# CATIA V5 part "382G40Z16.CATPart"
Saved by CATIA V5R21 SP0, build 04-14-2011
Part number: 382G40Z16
Bounding box of the stored display mesh (mm): x -131.403 to 131.403, y -131.403 to 131.403, z -20 to 20
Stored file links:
  C:\Users\ALI OZGUN\Desktop\alhan\TESLIMEDILEN3\382G40Z16.CATPart
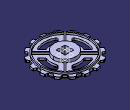
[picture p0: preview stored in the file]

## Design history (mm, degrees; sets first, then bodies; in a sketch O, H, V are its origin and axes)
Body1 (main body)
  Sketch1 on xy-plane, origin (0, 0, 0), H (1, 0, 0), V (0, 1, 0)
    circle A1 centre (0, 0) radius 132.5
    radius A1 = 132.5
  Pad1: profile Sketch1, direction (0, 0, 1), length 4.85, mirrored extent
  Sketch2 on end face of Pad1, origin (0, 0, 4.85), H (1, 0, 0), V (0, 1, 0)
    line L1 (-15.0612, 130.2617) -> (-10.5897, 120.8269)
    arc A1 centre (0, 0) radius 120 from (8.6385, 119.6887) to (-8.6385, 119.6887) ccw
    projected circle E1 centre (0, 0) radius 132.5 from edge [face of Pad1 from Sketch1.A1 | end face of Pad1]
    projected arc E2 centre (0, 0) radius 132.5 from (-17.127, 131.3884) to (-25.5392, 130.0154) ccw from edge [face of Pad1 from Sketch1.A1 | end face of Pad1]
    point P1 (-15.5, 131.1877)
    point P2 (-10, 119.5826)
    line L2 (15.0612, 130.2617) -> (10.5897, 120.8269)
    arc A2 centre (-8.7824, 121.6835) radius 2 from (-10.5897, 120.8269) to (-8.6385, 119.6887) ccw
    arc A3 centre (8.7824, 121.6835) radius 2 from (8.6385, 119.6887) to (10.5897, 120.8269) ccw
    line L3 (-31.529, 142.6538) -> (-25.5392, 130.0154)
    point P9 (-24.1515, 127.0874)
    point P10 (-19.2413, 116.7267)
    construction line L4 (-15.5, 131.1877) -> (-24.1515, 127.0874)
    construction line L5 (-10.5897, 120.8269) -> (-19.2413, 116.7267)
    offset circle E3 centre (0, 0) radius 146.0965 from edge [face of Pad1 from Sketch1.A1 | end face of Pad1]
    offset arc E4 centre (0, 0) radius 146.0965 from (31.529, 142.6538) to (-31.529, 142.6538) ccw from edge [face of Pad1 from Sketch1.A1 | end face of Pad1]
    line L6 (31.529, 142.6538) -> (25.5392, 130.0154)
    construction circle A4 centre (0, 0) radius 132.5
    arc A5 centre (0, 0) radius 132.5 from (17.127, 131.3884) to (25.5392, 130.0154) cw
    arc A6 centre (-16.8685, 129.4052) radius 2 from (-15.0612, 130.2617) to (-17.127, 131.3884) ccw
    arc A7 centre (16.8685, 129.4052) radius 2 from (17.127, 131.3884) to (15.0612, 130.2617) ccw
    distance P1 V = 15.5
    distance P2 V = 10
    radius A2 = 2
    radius A3 = 2 {= Sketch2.radius(A2)}
    distance L1 L3 = 9.574
    radius A6 = 2
    radius A7 = 2 {= Sketch2.radius(A6)}
    radius A1 = 120
    symmetry: L1 L2 V, E1 A4 V, L3 L6 V, E1 A5 V
    coincidence: L1 P2, A1 P2, P9 L3, P10 L3, P1 L1
    tangency: A2 L1, A2 A1, A3 A1, A3 L2, A6 L1, A6 E1, A7 A5, A7 L2
    perpendicularity: L4 L1, L4 L3, L5 L1, L5 L3
  Pocket1: profile Sketch2, direction (0, 0, -1), through (limit type 6)
  CircPattern1: of Pocket1, instances 16, angular step 22.5, axis from face of Pad1 from Sketch1.A1
  Sketch3 on xy-plane, origin (0, 0, 0), H (1, 0, 0), V (0, 1, 0)
    circle A1 centre (0, 0) radius 112
    radius A1 = 112
  Pad2: profile Sketch3, direction (0, 0, 1), length 13, mirrored extent, thin wall 5.5
  Sketch4 on xy-plane, origin (0, 0, 0), H (1, 0, 0), V (0, 1, 0)
    circle A1 centre (0, 0) radius 51.25
    radius A1 = 51.25
  Pad3: profile Sketch4, direction (0, 0, 1), length 20, mirrored extent
  Sketch5 on xy-plane, origin (0, 0, 0), H (1, 0, 0), V (0, 1, 0)
    line L1 (20, 20) -> (20, -20)
    line L2 (20, -20) -> (-20, -20)
    line L3 (-20, -20) -> (-20, 20)
    line L4 (-20, 20) -> (20, 20)
    length L1 = 40
    length L4 = 40
    vertical: L1 V, L3 V
    horizontal: L2 H, L4 H
    equidistance: L1 L3 O, L2 L4 O
  Pocket2: profile Sketch5, direction (0, 0, -1), length 21, mirrored extent
  Sketch6 on xy-plane, origin (0, 0, 0), H (1, 0, 0), V (0, 1, 0)
    line L1 (-77.2514, 77.2514) -> (-36.2392, 36.2392)
    point P1 (-77.2514, 77.2514)
    point P2 (77.2514, -77.2514)
    line L2 (77.2514, 77.2514) -> (36.2392, 36.2392)
    point P3 (77.2514, 77.2514)
    point P4 (-77.2514, -77.2514)
    reference projected circle E1 centre (0, 0) radius 109.25 from edge [end face of Pad2 | face of Pad2]
    reference projected circle E2 centre (0, 0) radius 51.25 from edge [face of Pad3 from Sketch4.A1 | end face of Pad3]
    point P5 (36.2392, 36.2392)
    line L3 (-36.2392, -36.2392) -> (-77.2514, -77.2514)
    point P6 (-36.2392, 36.2392)
    line L4 (36.2392, -36.2392) -> (77.2514, -77.2514)
    point P7 (-36.2392, -36.2392)
    point P8 (36.2392, -36.2392)
    angle L2 L1 = 90
    angle L1 V = 45
    coincidence: L1 O, L2 O, P1 E1, P3 E1, P2 E1, P4 E1, E2 P5, L2 L3, E2 P6, L1 L4, E2 P7, E2 P8
  Pad4: profile Sketch6, direction (0, 0, 1), length 13, mirrored extent, thin wall 6
  Sketch7 on xy-plane, origin (0, 0, 0), H (1, 0, 0), V (0, 1, 0)
    offset line E5 (60.9588, 93.4857) -> (19.9758, 52.5027) from edge [face of Pad4 | face of Pad4]
    offset line E6 (44.0319, 76.5588) -> (30.0645, 62.5914) from edge [face of Pad4 | face of Pad4]
    offset arc E7 centre (0, 0) radius 94.75 from (65.1333, 68.8129) to (-65.1333, 68.8129) ccw from edge [face of Pad4 | face of Pad2]
    offset arc E8 centre (0, 0) radius 94.75 from (42.7524, 84.5564) to (-42.7524, 84.5564) ccw from edge [face of Pad4 | face of Pad2]
    offset line E9 (-60.9588, 93.4857) -> (-19.9758, 52.5027) from edge [face of Pad4 | face of Pad4]
    offset line E10 (-44.0319, 76.5588) -> (-30.0645, 62.5914) from edge [face of Pad4 | face of Pad4]
    offset circle E11 centre (0, 0) radius 66.25 from edge [face of Pad3 from Sketch4.A1 | end face of Pad3]
    offset arc E12 centre (0, 0) radius 66.25 from (24.6673, 61.4865) to (-24.6673, 61.4865) ccw from edge [face of Pad3 from Sketch4.A1 | end face of Pad3]
    arc A1 centre (-40.4964, 80.0944) radius 5 from (-42.7524, 84.5564) to (-44.0319, 76.5588) ccw
    arc A2 centre (-26.529, 66.127) radius 5 from (-24.6673, 61.4865) to (-30.0645, 62.5914) cw
    arc A3 centre (26.529, 66.127) radius 5 from (30.0645, 62.5914) to (24.6673, 61.4865) cw
    arc A4 centre (40.4964, 80.0944) radius 5 from (42.7524, 84.5564) to (44.0319, 76.5588) cw
    radius A1 = 5
    radius A2 = 5 {= Sketch7.radius(A1)}
    radius A3 = 5 {= Sketch7.radius(A1)}
    radius A4 = 5 {= Sketch7.radius(A1)}
    tangency: A1 E7, A1 E9, A2 E11, A2 E9, A3 E5, A3 E11, A4 E7, A4 E5
  Pocket3: profile Sketch7, direction (0, 0, -1), length 13, mirrored extent
  CircPattern2: of Pocket3, instances 4, angular step 90, axis from face of Pad2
